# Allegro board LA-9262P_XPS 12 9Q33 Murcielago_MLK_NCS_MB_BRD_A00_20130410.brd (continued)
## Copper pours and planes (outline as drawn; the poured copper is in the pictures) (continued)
GND on TOP (solid shape): 210.81,28.25 210.81,27.92 210.8,27.9 210.8,26.6 210.85,26.55 210.85,25.57 210.77,25.49 210.12,25.49 210.04,25.57 210.04,26.5 209.91,26.63 209.79,26.63 209.71,26.64 209.64,26.63 209.29,26.63 209.25,26.64 209.21,26.64 209.14,26.67 209.11,26.74 209.11,26.78 209.11,27.21 209.11,27.25 209.11,27.28 209.11,27.71 209.11,27.75 209.11,27.78 209.11,28.21 209.11,28.27 209.18,28.33 210.73,28.33
GND on TOP (solid shape): 41.04,22.03 41.07,22.01 41.07,20.33 41.03,20.29 40.96,20.29 40.92,20.28 40.66,20.28 40.59,20.29 40.52,20.28 40.26,20.28 40.19,20.29 40.12,20.28 39.86,20.28 39.79,20.29 39.72,20.28 39.46,20.28 39.42,20.29 39.35,20.29 39.31,20.33 39.31,21.02 39.26,21.07 38.25,21.07 38.2,21.12 38.2,21.25 38.25,21.3 39.24,21.3 39.31,21.37 39.31,21.98 39.36,22.03 40.92,22.03
GND on TOP (solid shape): 221.24,48.8 221.99,47.83 223.12,48.29 230,48.29 230.35,48.15 230.49,47.8 230.49,45.15 230.35,44.8 230,44.66 222.49,44.66 221.36,45.12 220.61,44.15 220.61,42.76 217.74,42.76 217.35,43.14 217.35,44.54 218.37,45.55 218.37,49.36 219.01,50 219.92,50 220.73,50.81 221.24,50.81
GND on TOP (solid shape): 225.04,68.22 224.58,67.09 225.55,66.34 230.75,66.34 231.1,66.2 231.24,65.85 231.24,63.4 231.1,63.05 230.75,62.91 223.12,62.91 221.99,63.37 221.24,62.4 221.24,60.67 221.16,60.59 219.09,60.59 218.5,61.18 218.5,63.97 221.55,67.02 222.43,67.02 223.2,67.78 223.2,68.54 223.58,68.92 224.34,68.92 224.53,69.12 224.53,70.24 225.04,70.24
GND on TOP (solid shape): 220.61,30.05 221.34,29.08 222.48,29.52 222.49,29.54 231.2,29.54 231.55,29.4 231.69,29.05 231.69,28.51 231.69,26.19 232.39,25.49 232.39,20.16 231.69,19.46 231.69,17.24 232.79,17.24 232.99,17.04 232.99,15.76 232.79,15.56 232.14,15.56 232.14,16.07 232.48,16.07 232.48,16.73 231.13,16.73 230.96,16.91 230.96,18.62 231.18,18.84 231.18,20.07 231.29,20.17 231.29,27.4 230.17,28.51 225.75,28.51 225.23,29.03 222.75,29.03 221.39,28.55 220.24,29.43 218.37,29.43 217.35,30.44 217.35,30.95 217.86,31.46 219.85,31.46 220.1,31.71 220.1,41.14 220.61,41.14
GND on TOP (solid shape): outline of 495 points within 23.85,65.7 38.74,73.9
GND on TOP (solid shape): outline of 310 points within 0.51,0.51 231.24,88.54
GND on BOTTOM (solid shape): 139.8,81.12 139.8,77 137.71,77 137.69,77.03 137.69,81.09 137.89,81.29 139.63,81.29
GND on BOTTOM (solid shape): 200.98,22.06 200.98,19.27 200.86,19.14 198.19,19.14 198.19,22.19 198.7,22.69 200.35,22.69
GND on BOTTOM (solid shape): 212.44,66.69 212.44,65.34 212.39,65.29 209.29,65.29 209.29,66.66 209.39,66.76 212.36,66.76
GND on BOTTOM (solid shape): 30.83,22.61 30.83,20.95 30.51,20.64 28.36,20.64 27.92,21.09 27.92,22.56 28.1,22.75 30.69,22.75
GND on BOTTOM (solid shape): 51.51,66.69 51.51,66.26 51.38,66.13 44.14,66.13 44.01,66.26 44.01,67.14 44.14,67.27 50.93,67.27
GND on BOTTOM (solid shape): 66.36,21.04 66.36,19.14 66.24,19.01 63.19,19.01 63.06,19.14 63.06,21.42 63.32,21.68 65.73,21.68
GND on BOTTOM (solid shape): 79.36,47.73 79.36,46.35 79.2,46.19 69.79,46.19 69.61,46.36 69.61,47.66 69.8,47.84 79.25,47.84
GND on BOTTOM (solid shape): 167.08,34 167.08,30.96 166.95,30.82 165.46,30.82 165.34,30.94 165.34,33.95 165.46,34.07 167.01,34.07
GND on BOTTOM (solid shape): 188.72,79.53 188.72,76.54 188.48,76.3 186.57,76.3 186.13,76.74 186.13,79.46 186.38,79.72 188.54,79.72
GND on BOTTOM (solid shape): 195.65,27.03 195.65,26.1 195.52,25.97 192.49,25.97 192.35,26.11 192.35,26.96 192.53,27.14 195.54,27.14
GND on BOTTOM (solid shape): 206.09,48.58 206.09,45.45 205.95,45.32 204.53,45.32 204.13,45.71 204.13,48.3 204.49,48.65 206.01,48.65
GND on BOTTOM (solid shape): 207.02,27.28 207.02,26.13 206.88,26 203.74,26 203.6,26.14 203.6,27.29 203.71,27.4 206.89,27.4
GND on BOTTOM (solid shape): 214.81,48.82 214.81,47.25 214.64,47.08 211.97,47.08 211.76,47.29 211.76,48.74 212.02,49 214.63,49
GND on BOTTOM (solid shape): 221.24,56.82 221.24,54.43 221.2,54.39 220.82,54.39 219.86,55.36 219.86,55.9 220.81,56.86 221.2,56.86
GND on BOTTOM (solid shape): 121.08,78.66 121.08,77.75 120.86,77.53 118.64,77.53 118.44,77.74 118.44,78.73 118.51,78.8 120.94,78.8
GND on BOTTOM (solid shape): 126.37,85.43 126.37,84.68 126.2,84.51 122.87,84.51 122.84,84.54 122.84,85.46 122.91,85.52 126.28,85.52
GND on BOTTOM (solid shape): 140.2,42.72 140.2,41.37 140.11,41.27 135.25,41.27 135.17,41.35 135.17,42.62 135.46,42.92 140.01,42.92
GND on BOTTOM (solid shape): 220.16,28.6 220.16,27.48 219.75,27.07 218.29,27.07 218.15,27.2 218.15,28.75 218.36,28.96 219.8,28.96
GND on BOTTOM (solid shape): 140.99,76.95 140.99,75.86 140.91,75.78 139.14,75.78 139.03,75.88 139.03,76.77 139.11,76.85 139.85,76.85 140.04,77.04 140.9,77.04
GND on BOTTOM (solid shape): 51.51,70.33 51.51,69.43 51.25,69.18 44.14,69.18 44.01,69.3 44.01,70.19 44.14,70.32 50.55,70.32 50.75,70.51 51.33,70.51
GND on BOTTOM (solid shape): 51.51,64.2 51.51,63.46 51.12,63.08 44.27,63.08 44.01,63.33 44.01,64.1 44.14,64.22 50.68,64.22 50.82,64.37 51.34,64.37
GND on BOTTOM (solid shape): 113.95,70.93 113.95,70.42 113.92,70.39 113.51,70.39 113.26,70.14 112.28,70.14 112.22,70.21 112.22,70.78 112.46,71.02 113.86,71.02
GND on BOTTOM (solid shape): 164.79,36.28 167.84,36.28 168.09,36.03 168.09,34.89 167.84,34.63 163.39,34.63 163.14,34.89 163.14,36.28 163.39,36.54 164.54,36.54
GND on BOTTOM (solid shape): 38.48,74 38.48,71.81 34.48,71.81 33.97,71.29 31.78,71.29 31.46,71.6 31.46,73.25 31.76,73.55 33.97,73.55 34.43,74.01 38.46,74.01
GND on BOTTOM (solid shape): 78.18,21.55 78.18,19.39 77.92,19.14 74.97,19.14 74.86,19.25 74.86,19.4 74.86,19.4 74.86,21.8 74.99,21.93 77.8,21.93
GND on BOTTOM (solid shape): 115.83,24.66 119.07,24.66 119.39,24.35 119.39,19.88 118.92,19.41 118.9,19.41 118.81,19.31 114.47,19.31 113.88,19.89 113.88,24.35 114.2,24.67 115.82,24.67
GND on BOTTOM (solid shape): 116.71,81.19 116.71,79.56 116.7,79.55 115.86,79.55 115.73,79.42 115.73,78.47 115.67,78.4 115.11,78.4 115.05,78.4 114.98,78.47 114.98,79.36 115.01,79.39 115.01,81.24 116.66,81.24
GND on BOTTOM (solid shape): 150.87,41.55 150.97,41.57 152.88,41.57 153,41.44 153,40.5 152.85,40.35 149.42,40.35 149.23,40.54 149.23,41.45 149.35,41.57 150.77,41.57
GND on BOTTOM (solid shape): 146.67,82.68 146.67,81.86 146.55,81.74 146.54,81.74 146.32,81.52 141.74,81.52 141.66,81.6 141.66,82.03 141.8,82.17 142.9,82.17 143.55,82.82 146.53,82.82
GND on BOTTOM (solid shape): 171.18,34.21 172.86,34.21 172.87,34.2 172.87,32.52 171.17,32.52 171.17,33.39 171.07,33.48 170.09,33.48 170.02,33.56 170.02,34.16 170.11,34.25 171.13,34.25
GND on BOTTOM (solid shape): 23.1,25.25 23.1,23.42 22.58,22.9 21.77,22.9 21.64,23.04 21.64,23.29 21.79,23.44 22.05,23.44 22.1,23.44 22.15,23.44 22.38,23.44 22.54,23.6 22.54,24.23 22.46,24.31 22.46,25.31 22.54,25.39 22.96,25.39
GND on BOTTOM (solid shape): 207.49,68.85 207.49,67.22 207.44,67.17 206.6,67.17 206.52,67.09 206.52,66.1 206.45,66.03 205.84,66.03 205.77,66.1 205.77,67.02 205.8,67.04 205.8,68.79 205.83,68.85 205.9,68.87 207.46,68.87
GND on BOTTOM (solid shape): 216.86,70 216.86,65.62 216.8,65.56 215.93,65.56 215.85,65.64 215.85,67.14 215.58,67.41 215.58,67.58 215.59,67.59 215.64,67.73 215.64,67.87 215.61,68.11 215.46,68.29 215.46,70 215.6,70.14 216.72,70.14
GND on BOTTOM (solid shape): 24.87,77.08 24.87,75.59 24.72,75.44 24.04,75.44 23.73,75.13 23.73,73.82 23.95,73.6 24.61,73.6 24.88,73.6 25.22,73.95 29.29,73.95 29.33,73.92 29.33,71.75 29.3,71.73 25.27,71.73 24.28,70.74 22.47,70.74 22.25,70.97 22.25,74.91 22.28,74.93 22.5,75.27 22.28,75.62 22.25,75.63 22.25,76.76 22.68,77.19 24.76,77.19
GND on BOTTOM (solid shape): 225.04,68.22 224.58,67.09 225.55,66.34 230.75,66.34 231.1,66.2 231.24,65.85 231.24,63.4 231.1,63.05 230.75,62.91 223.12,62.91 221.99,63.37 221.24,62.4 221.24,60.57 219.5,60.57 218.51,61.56 218.51,63.79 223.44,68.72 224.23,68.72 224.53,69.02 224.53,70.24 225.04,70.24
GND on BOTTOM (solid shape): 221.24,50.7 221.24,48.8 221.99,47.83 223.12,48.29 230,48.29 230.35,48.15 230.49,47.8 230.49,45.15 230.35,44.8 230,44.66 222.49,44.66 221.36,45.12 220.61,44.15 220.61,42.74 217.62,42.74 216.83,43.52 216.83,47.84 219.07,50.08 220.13,50.08 220.74,50.69 220.81,50.76 221.18,50.76
GND on BOTTOM (solid shape): outline of 407 points within 61.58,77.3 82.83,79.21
GND on BOTTOM (solid shape): outline of 1532 points within 179.9,45.08 199.59,74.18
GND on BOTTOM (solid shape): outline of 424 points within 0.51,0.51 232.99,88.54
GND on IN1 (solid shape): 221.24,54.39 219.93,54.39 219.93,56.38 220.34,56.38 220.85,56.88 221.24,56.88
GND on IN1 (solid shape): 221.24,48.8 221.99,47.83 223.12,48.29 230,48.29 230.35,48.15 230.49,47.8 230.49,45.15 230.35,44.8 230,44.66 222.49,44.66 221.36,45.12 220.61,44.15 220.61,42.79 217.85,42.79 217.42,43.22 217.42,43.8 218.46,44.84 218.46,49.52 219.76,50.81 221.24,50.81
GND on IN1 (solid shape): 225.04,68.22 224.58,67.09 225.55,66.34 230.75,66.34 231.1,66.2 231.24,65.85 231.24,63.4 231.1,63.05 230.75,62.91 223.12,62.91 221.99,63.37 221.24,62.4 221.24,60.36 220.73,60.36 220.73,60.41 219.53,60.41 218.38,61.56 218.38,63.84 221.69,67.14 222.19,67.14 223.34,68.29 223.34,68.54 224.53,69.74 224.53,70.24 225.04,70.24
GND on IN1 (solid shape): outline of 313 points within 21.62,64.67 38.22,73.94
GND on IN1 (solid shape): outline of 374 points within 0.51,0.51 232.99,88.54
GND on IN2 (solid shape): 221.24,56.85 221.24,54.43 221.18,54.37 220.84,54.37 219.91,55.3 219.91,56.03 220.79,56.91 221.18,56.91
GND on IN2 (solid shape): 221.24,48.8 221.99,47.83 223.12,48.29 230,48.29 230.35,48.15 230.49,47.8 230.49,45.15 230.35,44.8 230,44.66 222.49,44.66 221.36,45.12 220.61,44.15 220.61,42.81 217.8,42.81 217.01,43.6 217.01,48.35 219.43,50.76 221.24,50.76
GND on IN2 (solid shape): 225.04,68.22 224.58,67.09 225.55,66.34 230.75,66.34 231.1,66.2 231.24,65.85 231.24,63.4 231.1,63.05 230.75,62.91 223.12,62.91 221.99,63.37 221.24,62.4 221.24,60.81 221.13,60.69 220.73,60.69 220.43,61 219.15,61 218.51,61.63 218.51,64.07 221.36,66.92 221.63,66.92 223.44,68.72 224.28,68.72 224.53,68.97 224.53,70.22 225.04,70.22
GND on IN2 (solid shape): outline of 291 points within 21.38,65.43 38.21,73.87
GND on IN2 (solid shape): outline of 379 points within 0.51,0.51 232.99,88.54
GND on IN3 (solid shape): 221.24,56.79 221.24,54.41 221.2,54.37 220.84,54.37 219.93,55.27 219.93,56.01 220.81,56.88 221.15,56.88
GND on IN3 (solid shape): 221.24,50.7 221.24,48.8 221.99,47.83 223.12,48.29 230,48.29 230.35,48.15 230.49,47.8 230.49,45.15 230.35,44.8 230,44.66 222.49,44.66 221.36,45.12 220.61,44.15 220.61,42.74 217.77,42.74 216.99,43.52 216.99,48.07 219.15,50.23 220.25,50.23 220.84,50.81 221.13,50.81
GND on IN3 (solid shape): 225.04,68.22 224.58,67.09 225.55,66.34 230.75,66.34 231.1,66.2 231.24,65.85 231.24,63.4 231.1,63.05 230.75,62.91 223.12,62.91 221.99,63.37 221.24,62.4 221.24,60.62 219.15,60.62 218.46,61.3 218.46,64 221.33,66.87 221.56,66.87 223.44,68.75 224.41,68.75 224.53,68.87 224.53,70.24 225.04,70.24
GND on IN3 (solid shape): outline of 179 points within 22.72,68.49 38.17,74.6
GND on IN3 (solid shape): outline of 389 points within 0.51,0.51 232.99,88.54
GND on IN4 (solid shape): 221.24,56.85 221.24,54.41 221.2,54.37 220.84,54.37 219.93,55.27 219.93,56.01 220.81,56.88 221.2,56.88
GND on IN4 (solid shape): 221.24,50.66 221.24,48.8 221.99,47.83 223.12,48.29 230,48.29 230.35,48.15 230.49,47.8 230.49,45.15 230.35,44.8 230,44.66 222.49,44.66 221.36,45.12 220.61,44.15 220.61,42.76 217.72,42.76 216.92,43.56 216.92,48.77 218.92,50.76 221.14,50.76
GND on IN4 (solid shape): 225.04,68.22 224.58,67.09 225.55,66.34 230.75,66.34 231.1,66.2 231.24,65.85 231.24,63.4 231.1,63.05 230.75,62.91 223.12,62.91 221.99,63.37 221.24,62.4 221.24,60.67 219.3,60.67 218.49,61.48 218.49,63.97 221.46,66.94 221.66,66.94 223.44,68.72 224.31,68.72 224.53,68.95 224.53,70.24 225.04,70.24
GND on IN4 (solid shape): outline of 113 points within 25.1,69.66 38.17,74.39
GND on IN4 (solid shape): outline of 383 points within 0.51,0.51 232.99,88.54
GND on GND1: outline of 201 points within 0.51,0.51 232.99,88.54 ; 3 cut-outs
GND on GND2, GND4: outline of 201 points within 0.51,0.51 232.99,88.54 ; 2 cut-outs
GND on GND3: outline of 323 points within 0.51,0.51 232.99,88.54 ; 2 cut-outs
GND on VCC: 60.79,13.75 58.5,11.46 56.21,13.75 56.21,16.55 55.77,17.62 54.7,18.06 47.56,18.06 47.56,18.08 47.64,18.33 47.56,18.57 47.56,23.31 46.65,24.22 14.43,24.22 13.65,23.44 13.65,18.56 13.58,18.33 13.65,18.09 13.65,18.06 1,18.06 0.65,18.2 0.51,18.55 0.51,28 0.58,28.25 0.77,28.43 9.82,35.93 15.08,46.44 21.99,46.44 22.01,46.42 22.22,46.42 22.25,46.44 22.26,46.44 22.41,46.59 22.41,46.6 26.07,50.25 29.37,50.25 35.47,56.35 45.88,56.35 52.74,63.21 55.79,63.21 57.57,64.99 63.41,64.99 63.92,65.49 83.77,65.49 84.13,65.14 84.13,65.13 84.52,64.74 84.53,64.74 85.54,63.74 85.54,63.59 85.8,63.59 87.72,63.59 88.21,63.1 88.21,61.71 88.99,60.92 91.52,60.92 92.79,59.65 94.06,59.65 96.32,57.39 96.32,54.21 98.62,51.93 98.62,51.29 99.15,50.76 105.2,50.76 105.35,50.91 105.35,50.92 110.91,56.48 111.46,56.48 112.35,55.59 124.29,55.59 126.55,53.32 126.55,29.28 125.68,28.41 120.86,28.41 116.67,24.22 76.66,24.22 75.5,23.05 75.5,18.06 62.3,18.06 61.23,17.62 60.79,16.55
GND on VCC: 230.49,45.15 230.35,44.8 230,44.66 222.49,44.66 222.06,45.06 221.48,45.15 217.39,49.24 201.26,49.24 200.35,48.33 200.35,46.19 196.14,46.19 195.52,46.8 195.51,61.2 198.32,64 198.32,70.21 203.78,75.68 203.78,78.72 204.13,78.59 204.5,78.54 213.08,78.54 214.04,78.88 214.56,79.75 217,81.74 219.44,79.75 219.96,78.88 220.92,78.54 230.75,78.54 231.1,78.4 231.24,78.05 231.24,76.75 231.1,76.4 230.75,76.26 225.55,76.26 224.58,75.51 225.04,74.38 225.04,68.22 224.58,67.09 225.55,66.34 230.75,66.34 231.1,66.2 231.24,65.85 231.24,63.4 231.1,63.05 230.75,62.91 223.12,62.91 221.99,63.37 221.24,62.4 221.24,48.8 221.99,47.83 223.12,48.29 230,48.29 230.35,48.15 230.49,47.8
GND on VCC: 18.18,63.46 21.01,79.51 21.01,88.05 21.15,88.4 21.5,88.54 23.39,88.54 23.57,88.5 23.73,88.4 25.29,86.84 31.43,86.84 32.56,86.57 33.44,85.81 34.33,84.88 35.42,84.19 34.6,83.38 34.6,75.62 30.3,71.31 30.3,70.93 29.94,70.57 29.43,70.57 22.32,63.46
GND on VCC: 232.99,1 232.85,0.65 232.5,0.51 230,0.51 229.65,0.65 229.51,1 229.51,1.5 229.07,2.57 228,3.01 224.5,3.01 224.15,3.15 224.01,3.5 224.01,14.55 223.24,16.74 221.28,17.97 221.37,18.06 221.37,29.07 222.01,29.12 222.49,29.54 231.2,29.54 231.55,29.4 231.69,29.05 231.69,26.19 232.39,25.49 232.39,20.16 231.69,19.46 231.69,17.24 232.79,17.24 232.99,17.04 232.99,15.76 232.79,15.56 231.69,15.56 231.69,13.54 232.79,13.54 232.99,13.34 232.99,12.16 232.79,11.96 231.69,11.96 231.69,9.94 232.79,9.94 232.99,9.74 232.99,8.56 232.79,8.36 231.69,8.36 231.69,6.34 232.79,6.34 232.99,6.14 232.99,4.96 232.79,4.76 231.69,4.76 231.69,2.74 232.79,2.74 232.99,2.54
GND on GND5: outline of 201 points within 0.51,0.51 232.99,88.54 ; 1 cut-out
VDD_+1.2V on TOP (solid shape): 44.94,21.82 44.94,21.81 45.17,21.62 45.47,21.65 45.85,21.65 45.99,21.61 46.13,21.61 46.16,21.62 46.25,21.53 46.25,21.02 46.12,20.89 44.09,20.89 43.83,20.64 43.83,20 43.71,19.88 43.33,19.88 43.2,20 43.2,20.43 43.33,20.7 43.21,20.98 43.2,21 43.2,21.02 43.07,21.15 43.07,21.78 43.2,21.91 44.85,21.91
VIN on TOP (solid shape): 173.43,42.65 173.43,41.17 172.97,40.72 171.87,40.72 171.87,40.74 169.15,40.74 169.01,40.88 169.01,41.98 169.22,42.2 169.22,42.82 169.34,42.94 173.14,42.94
VIN on TOP (solid shape): 195.24,80.01 198.67,80.01 198.94,79.75 198.94,78.89 198.75,78.7 195.69,78.7 195.42,78.97 194.83,78.97 194.57,79.22 193.05,79.22 192.91,79.36 192.91,80.4 193.1,80.59 194.66,80.59
VIN on IN2 (solid shape): 173.55,42.13 173.55,41.24 173.43,41.11 171.65,41.11 171.27,41.49 169.23,41.49 169.11,41.62 169.11,43.14 169.36,43.4 172.28,43.4
VIN on IN2 (solid shape): 147.23,48.48 147.23,46.37 146.31,45.46 144.83,45.46 144.53,45.15 144.53,44.55 144.22,44.24 142.3,44.24 141.91,44.63 141.91,45.81 142.07,45.97 144.78,45.97 144.79,45.91 144.8,45.86 144.82,45.8 144.85,45.76 144.88,45.71 144.92,45.67 144.97,45.64 145.02,45.61 145.07,45.6 145.12,45.59 145.18,45.58 145.23,45.59 145.29,45.6 145.34,45.63 145.39,45.66 145.43,45.69 145.47,45.73 145.5,45.78 145.52,45.83 145.54,45.88 145.55,45.94 145.55,45.99 145.54,46.05 145.52,46.1 145.5,46.15 145.47,46.2 145.43,46.24 145.39,46.28 145.34,46.31 145.29,46.33 145.23,46.34 145.18,46.35 145.12,46.35 145.07,46.34 145.02,46.32 144.97,46.29 144.92,46.26 144.88,46.22 144.85,46.18 144.82,46.13 144.8,46.08 144.79,46.02 144.78,45.97 142.07,45.97 143.59,47.49 144.04,47.49 144.79,48.23 145.84,48.23 146.36,48.75 146.95,48.75
VIN on VCC: 169.97,40.73 169.09,41.6 169.09,44.54 170.09,44.54 172.23,46.69 172.23,48.35 175.53,51.65 175.53,56.89 175.41,57.14 172.28,60.27 172.28,69.02 173.92,70.66 173.92,74.28 176.31,76.67 188.63,76.67 192.44,80.48 197.78,80.48 198.43,81.14 198.43,82.15 198.71,82.07 199,82.04 202.5,82.04 202.85,81.9 202.99,81.55 202.99,80.05 203.06,79.59 203.27,79.17 203.27,75.89 197.81,70.43 197.81,64.21 195.15,61.56 190.07,61.56 189.41,60.9 189.41,49.72 185.36,45.67 185.36,45.66 180.43,40.73
1.2_PGND on TOP (solid shape): 116.39,48.39 116.39,47.35 116.66,47.08 119.64,47.08 119.69,47.03 119.69,45.94 119.56,45.81 119.56,45.05 119.56,44.2 119.38,44.02 118.18,44.02 118.04,44.16 118.04,44.92 117.79,45.17 117.02,45.17 116.83,45.36 116.83,45.91 116.49,46.25 116.48,46.25 115.96,46.77 115.6,46.77 115.53,46.85 115.53,48.43 115.64,48.54 116.24,48.54
1.2_PGND on GND1: 118.53,44.28 118.42,44.39 118.42,44.9 117.89,45.43 115.75,45.43 115.54,45.63 115.54,49.09 118.35,51.9 122.25,51.9 122.61,51.55 122.61,46.42 121.75,45.55 121.24,45.55 119.97,44.28
+INV_PWR_SRC on TOP (solid shape): 160.22,82.01 160.53,82.01 161,81.54 161.02,81.43 160.93,81.37 160.6,80.86 161.18,80.68 161.22,80.7 161.27,80.7 161.47,80.7 161.55,80.62 161.55,80.02 161.51,79.98 161.51,79.64 161.82,79.34 164.68,79.34 164.68,79.33 165.93,79.33 166.95,78.31 166.95,76.49 166.76,76.3 165.96,76.3 165.92,76.34 165.92,76.62 165.49,77.05 161.38,77.05 160.57,77.87 160.57,78.3 160.72,78.44 160.78,78.65 160.61,78.96 160.25,78.99 160.22,78.98 159.85,79.35 158.64,79.35 158.56,79.43 158.56,80.45 157.63,81.38 157.63,81.97 157.67,82.01 160.22,82.01
+INV_PWR_SRC on BOTTOM (solid shape): 160.28,81.66 160.28,80.58 160.18,80.48 159.49,80.48 159.39,80.38 159.39,79.08 159.34,79.03 158.68,79.03 158.6,79.11 158.6,80.3 158.44,80.47 158.44,81.72 158.55,81.84 160.1,81.84
+LCDVDD on TOP (solid shape): 171.67,75.64 171.67,75.07 171.7,75.04 171.7,73.65 171.7,73.65 171.7,73.51 171.5,73.32 170.46,73.32 170.21,73.56 170.21,75.45 170.53,75.77 171.53,75.77
+LCDVDD on BOTTOM (solid shape): 171.87,76.58 171.87,75.82 171.69,75.64 171.69,75.48 171.68,75.45 171.69,75.42 171.69,74.78 171.52,74.62 170.29,74.62 170.16,74.76 170.16,76.54 170.26,76.64 171.81,76.64
+LCDVDD on BOTTOM (solid shape): 179.89,80.28 179.89,79.08 180.06,78.92 180.06,77.99 179.9,77.84 179.9,77.38 179.77,77.24 179.77,76.67 179.62,76.52 177.72,76.52 177.58,76.66 177.58,78.77 177.69,78.88 178.9,78.88 179.1,79.08 179.1,80.3 179.18,80.38 179.79,80.38
+LCDVDD on VCC: 170.22,74.51 169.86,74.87 169.86,79.49 170.72,80.35 180.17,80.35 181.16,79.36 181.16,77.56 180.77,77.18 176.1,77.18 173.43,74.51
+VCHGR on BOTTOM (solid shape): outline of 118 points within 135.12,32.74 142.81,41.87
+VREFCA on IN1 (solid shape): outline of 5910 points within 16.24,28.66 67.76,34.51
+VREFCA on IN2 (solid shape): outline of 4646 points within 55.06,28.41 103.83,33.62
+VREFDQ_A on IN1 (solid shape): outline of 3930 points within 24.84,34.89 63.19,43.27
+VREFDQ_B on IN2 (solid shape): outline of 6567 points within 64.08,34.25 110.69,42.63
ADPIN on TOP (solid shape): 196.51,84 196.51,81.94 197.38,81.08 197.38,80.57 197.2,80.39 196.44,80.39 196.44,80.39 195.21,80.39 194.69,80.91 193.06,80.91 192.96,81 192.96,82.06 193.38,82.48 193.38,83.82 193.59,84.04 196.48,84.04
ADPIN on BOTTOM (solid shape): 196.2,83.22 196.2,80.81 195.65,80.26 190.94,80.26 190.7,80.5 190.7,82.11 190.98,82.39 192.43,82.39 193.36,83.32 196.09,83.32
B+ on TOP (solid shape): 201.45,46.24 201.45,44.31 201.25,44.11 200.21,44.11 200.01,44.31 200.01,46.11 200.25,46.35 201.35,46.35
B+ on TOP (solid shape): 210.67,70.41 210.67,69.61 210.24,69.18 206.2,69.18 206.02,69.35 206.02,70.48 206.12,70.58 210.5,70.58
B+ on TOP (solid shape): 201.99,36.58 201.99,35.57 202.45,35.12 202.45,34.43 202.22,34.2 201.73,34.2 201.23,34.71 200.67,34.71 200.58,34.8 200.58,36.58 200.69,36.69 201.87,36.69
B+ on TOP (solid shape): 203.35,26.13 203.35,24.99 203.18,24.82 202.31,24.82 201.9,24.41 201.9,22.03 198.71,18.83 193.1,18.83 192.92,19.01 192.92,20.54 192.92,20.54 192.92,20.9 193.21,21.19 196.54,21.19 198.58,23.23 198.58,25.29 199.57,26.28 203.2,26.28
B+ on TOP (solid shape): 166.05,85.94 166.05,85.05 165.92,84.92 163.51,84.92 163.39,85.04 163.4,85.07 163.43,85.27 163.38,85.46 163.38,85.47 163.38,85.81 163.76,86.19 165.79,86.19
B+ on TOP (solid shape): 122.46,83.14 122.46,80.57 121.59,79.69 118.81,79.69 118.76,79.64 118.75,79.64 118.37,79.26 116.61,79.26 116.61,79.26 116.55,79.26 115.87,78.58 115.04,78.58 114.96,78.66 114.96,81.08 115.36,81.47 117.97,81.47 118.28,81.77 119.39,81.77 120.19,82.58 120.26,82.66 120.32,82.75 120.45,82.88 120.45,83.11 120.62,83.28 120.63,83.28 120.96,83.62 121.98,83.62
B+ on TOP (solid shape): outline of 109 points within 157.51,79.53 163.84,83.91
B+ on BOTTOM (solid shape): 170.38,25.17 170.38,23.44 170.05,23.11 167,23.11 166.67,23.44 166.67,25.25 166.86,25.44 170.1,25.44
B+ on BOTTOM (solid shape): 86.84,21.19 86.84,19.56 86.54,19.26 83.8,19.26 83.52,19.54 83.52,20.96 83.85,21.29 86.74,21.29
B+ on BOTTOM (solid shape): 122.41,83.17 122.41,80.73 122.16,80.48 121.41,80.48 121.41,81.01 120.95,81.01 120.95,80.48 120.58,80.48 120.12,80.94 120.12,82.88 121,83.75 121.83,83.75
B+ on BOTTOM (solid shape): 191.92,29.98 191.92,27.85 191.84,27.77 187.35,27.77 186.42,28.71 184.37,28.71 184.29,28.78 184.29,29.84 184.38,29.92 186.45,29.92 187.1,30.57 191.33,30.57
B+ on BOTTOM (solid shape): 211.04,70.27 211.04,69.06 210.93,68.95 210.46,68.95 210.46,69.48 210.02,69.48 210.02,68.95 209.04,68.95 208.92,69.06 208.92,69.25 208.91,69.27 208.91,69.31 208.77,69.45 208.77,69.45 208.69,69.54 208.69,70.31 208.84,70.47 210.84,70.47
B+ on BOTTOM (solid shape): 39.55,82.14 39.55,81.18 39.56,81.17 39.56,78.12 39.21,77.77 36.88,77.77 36.87,77.78 36.87,79.22 36.99,79.34 36.99,80.78 36.98,80.8 36.46,80.8 36.46,81.04 36.99,81.04 37,81.05 37,81.6 36.46,81.6 36.46,81.83 37,81.83 37,82.32 37.13,82.45 39.24,82.45
B+ on BOTTOM (solid shape): outline of 2376 points within 135.17,35.9 157.13,83.02
B+ on IN1 (solid shape): outline of 5778 points within 190.6,18.83 218.23,70.6
B+ on IN4 (solid shape): outline of 478 points within 119.96,76.89 152.6,85.94
B+ on VCC: 108.8,73.06 106.84,75.02 103.85,75.02 100.67,78.19 59.39,78.19 56.85,75.65 35.11,75.65 35.11,83.17 35.93,83.99 39.04,83.98 41.56,85.81 42.44,86.57 43.57,86.84 111.43,86.84 112.56,86.57 113.44,85.81 117.5,83.74 121.56,85.81 122.44,86.57 123.57,86.84 131.39,86.84 131.61,86.86 131.83,86.91 131.83,86.64 132.13,86.35 134.19,86.35 136.07,84.46 136.07,83.7 136.37,83.4 136.79,83.4 136.81,83.42 137.34,82.99 138,82.84 141,82.84 141.86,83.11 142.41,83.81 142.44,83.78 143.22,83.78 144.11,84.67 150.76,84.67 151.06,84.97 151.06,85.06 151.33,85.32 151.33,85.36 151.37,85.36 151.67,85.65 151.67,85.68 151.9,85.91 151.9,86.02 152.03,86.15 152.03,86.71 152.05,86.73 152.05,86.84 165.32,86.84 165.57,86.59 154.38,75.4 132.73,75.4 125.92,82.21 122.75,82.21 121.39,80.85 121.39,78.35 119.84,76.8 113.49,76.8 109.76,73.06
B+ on VCC: 132.85,18.2 132.5,18.06 76,18.06 76,22.83 76.02,22.84 76.02,22.86 76.87,23.71 116.88,23.71 121.07,27.9 130.97,27.9 141.39,38.32 152.86,38.32 153.22,37.96 153.22,31.61 160.73,24.09 198.09,24.09 198.57,23.61 198.57,18.56 198.07,18.06 179.5,18.06 179.15,18.2 178.57,19.62 177.5,20.06 134.5,20.06 133.43,19.62
BATT+ on BOTTOM (solid shape): outline of 345 points within 126.47,30.57 134.27,41.81
BATT++ on BOTTOM (solid shape): outline of 632 points within 119.97,19.27 131.01,41.08
BTST on TOP (solid shape): 152.92,43.09 152.92,42.35 152.79,42.23 152.07,42.23 151.49,42.81 150.47,42.81 150.4,42.88 150.4,43 150.48,43.07 151.98,43.07 152.1,43.19 152.81,43.19
CHG_LGATE on TOP (solid shape): 157.64,33.94 157.64,33.14 157.53,33.03 156.52,33.03 156.4,33.15 156.4,33.93 156.59,34.12 157.45,34.12
CHG_LGATE on TOP (solid shape): 150.43,42.13 150.93,42.13 151.06,42 151.06,41.46 150.78,41.18 150.18,41.18 150.08,41.27 150.08,42.16 150.17,42.25 150.3,42.25
CHG_LGATE on IN2 (solid shape): 157.68,33.62 157.68,32.73 157.55,32.6 154.76,32.6 154.5,32.85 154.5,33.62 154.63,33.74 157.55,33.74
CHG_LGATE on IN2 (solid shape): 151.28,42.04 151.28,42.02 151.29,41.92 151.32,41.83 151.33,41.82 151.33,41.11 151.07,40.86 149.93,40.86 149.68,41.11 149.68,42 149.93,42.25 150.57,42.25 150.82,42.15 151.07,42.26
CHG_LX on TOP (solid shape): 155.59,45.34 155.59,39.75 156.14,39.2 159.44,39.2 159.7,38.95 159.7,36.92 160.46,36.16 160.46,35.65 161.38,34.73 161.38,33.97 160.93,33.52 158.28,33.52 158.09,33.71 158.09,35.73 156.39,37.43 154.11,37.43 153.85,37.68 153.85,39.97 154.66,40.77 154.66,41.08 154.5,41.24 154.5,41.42 154.49,41.43 154.49,44.89 154.29,45.1 153.4,45.1 153.22,44.92 153.22,44.16 153.04,43.98 151.78,43.98 151.61,43.81 150.48,43.81 150.41,43.88 150.41,44 150.49,44.08 151.38,44.08 151.7,44.41 151.71,44.41 151.95,44.55 152.09,44.79 152.1,44.81 152.11,44.89 152.12,44.95 152.12,45.04 152.5,45.43 152.62,45.61 152.66,45.83 152.69,45.91 152.76,45.94 155,45.94
CHG_LX on BOTTOM (solid shape): outline of 85 points within 157.93,33.74 162.38,40.98
CHG_UGATE on TOP (solid shape): 152.99,43.75 152.99,43.42 152.89,43.32 152,43.32 151.99,43.31 150.49,43.31 150.41,43.38 150.41,43.51 150.49,43.59 151.58,43.59 151.82,43.83 152.92,43.83
CHG_UGATE on TOP (solid shape): 161.86,38.89 161.86,36.34 161.92,36.28 161.92,35.63 161.77,35.48 160.88,35.48 160.71,35.65 160.71,36.16 160.13,36.74 160.13,38.93 160.29,39.09 161.66,39.09
CHG_UGATE on IN2 (solid shape): 153.74,43.52 153.74,42.76 153.61,42.63 151.71,42.63 151.58,42.76 151.58,43.52 151.84,43.78 153.49,43.78
CHG_UGATE on IN2 (solid shape): 162.12,38.32 162.12,35.78 161.87,35.52 160.85,35.52 160.6,35.78 160.6,38.32 160.85,38.57 161.87,38.57
COMP on TOP (solid shape): 31.08,85.45 31.08,85.18 31.53,84.72 31.96,84.72 32.19,84.49 32.19,83.65 32.06,83.53 31.43,83.53 31.3,83.4 31.3,82.89 31.17,82.77 30.41,82.77 30.28,82.89 30.28,85.4 30.46,85.58 30.95,85.58
CPU_B+ on BOTTOM (solid shape): 38.75,67.96 38.75,63.92 38.49,63.65 35.74,63.65 35.5,63.89 35.5,67.53 36.27,68.29 38.42,68.29
CPU_B+ on BOTTOM (solid shape): outline of 428 points within 23.91,73.88 36.97,82.38
CPU_B+ on IN1 (solid shape): outline of 945 points within 23.91,66.26 41.35,81.27
DCIN_GND on BOTTOM (solid shape): 192.76,79.54 192.76,75.78 192.48,75.5 190.21,75.5 190.08,75.37 189.52,75.37 189.25,75.64 189.25,78.04 189.96,78.04 189.96,77.99 189.98,77.93 190,77.88 190.02,77.83 190.06,77.79 190.1,77.75 190.14,77.72 190.19,77.69 190.25,77.67 190.3,77.66 190.36,77.66 190.41,77.67 190.47,77.68 190.52,77.7 190.56,77.73 190.61,77.77 190.64,77.81 190.68,77.85 190.7,77.9 190.72,77.96 190.72,78.01 190.72,78.07 190.72,78.12 190.7,78.18 190.68,78.23 190.64,78.28 190.61,78.32 190.56,78.35 190.52,78.38 190.47,78.4 190.41,78.42 190.36,78.42 190.3,78.42 190.25,78.41 190.19,78.39 190.14,78.37 190.1,78.34 190.06,78.3 190.02,78.25 190,78.2 189.98,78.15 189.96,78.1 189.96,78.04 189.25,78.04 189.25,79.49 189.59,79.83 192.47,79.83
DH_+1.2V on TOP (solid shape): 50.07,22.82 51,22.82 51.07,22.74 51.07,22.45 50.95,22.33 49.93,22.33 49.82,22.44 49.49,22.44 49.38,22.34 49.38,21.81 49.23,21.65 48.83,21.65 48.67,21.81 48.67,22.87 48.8,23 49.89,23
DH_+1.2V on TOP (solid shape): 43.61,24.33 43.61,23.86 43.71,23.76 43.71,23.75 43.74,23.62 43.8,23.5 43.8,23.49 43.8,23.1 43.68,22.98 43.34,23.08 42.99,22.96 42.98,22.95 42.79,22.95 42.68,23.06 42.68,23.55 42.52,23.71 41,23.71 40.76,23.46 40.76,22.33 40.7,22.28 40.57,22.28 40.52,22.33 40.52,23.88 40.44,23.96 40.44,24.27 40.62,24.45 43.49,24.45
DH_+1.2V on IN1 (solid shape): 44.65,23.33 44.65,22.57 44.52,22.44 43.25,22.44 42.74,22.95 42.74,23.2 43,23.46 44.52,23.46
DH_+1.2V on IN1 (solid shape): 50.36,22.95 50.36,21.3 50.11,21.04 48.97,21.04 48.71,21.3 48.71,22.95 48.84,23.08 50.24,23.08
DL_+1.2V on TOP (solid shape): 42.84,22.62 42.84,22.29 42.69,22.14 42.41,22.14 42.16,21.88 41.35,21.88 41.28,21.95 41.28,22.17 41.85,22.75 42.72,22.75
DL_+1.2V on TOP (solid shape): 53.8,22.06 53.8,21.73 53.63,21.55 51.67,21.55 51.03,20.91 50.22,20.91 50.09,21.04 50.09,21.85 50.22,21.98 51.16,21.98 51.37,22.19 53.68,22.19
DL_+1.2V on IN4 (solid shape): 53.82,22.26 53.82,21.7 53.54,21.42 50.49,21.42 50.36,21.55 50.36,22.31 50.49,22.44 53.64,22.44
DL_+1.2V on IN4 (solid shape): 42.79,22.82 42.92,22.8 43.05,22.82 43.06,22.82 43.42,22.82 43.43,22.82 43.56,22.8 43.69,22.82 43.69,22.82 43.89,22.82 43.89,21.81 42.11,21.81 41.73,22.19 41.73,22.57 41.98,22.82 42.78,22.82
INV_PWM_R on TOP (solid shape): 159.99,78.95 159.99,78.35 159.9,78.14 160,77.93 160,77.8 161.97,75.82 162.63,75.82 162.63,75.82 163.28,75.82 163.76,75.34 163.91,75.34 164.03,75.22 164.03,73.05 163.87,72.88 162.52,72.88 161.96,73.44 160.74,73.44 160.43,73.75 160.43,75.67 160.26,75.85 159.23,75.85 159.1,75.97 159.1,77.3 158.8,77.61 158.8,79.05 158.93,79.18 159.76,79.18
P1 on TOP (solid shape): 164.92,45.03 164.92,44.19 164.57,43.85 164.57,41.56 165.09,41.04 165.09,40.61 165.3,40.39 165.74,40.39 166,40.13 166,39.53 165.96,39.46 165.61,39.11 165.61,38.64 165.94,38.32 166.24,38.32 166.95,37.61 166.98,37.57 168.12,37.57 168.21,37.49 168.21,36.92 167.23,36.92 166.94,36.85 166.72,36.66 166.7,36.64 166.5,36.64 166.3,36.44 166.3,36.13 166.48,35.95 166.52,35.95 166.59,35.93 166.66,35.93 166.7,35.93 166.72,35.91 166.94,35.72 167.23,35.65 167.69,35.65 167.73,35.55 167.73,35.44 167.64,35.39 165.6,35.39 164.64,36.36 164.63,36.37 164.54,36.53 164.38,36.62 164.37,36.63 164.1,36.9 164.1,39.5 163.38,40.22 163.38,45.05 163.63,45.3 164.65,45.3
REGN on TOP (solid shape): 151.95,42.13 151.95,40.83 153.48,39.3 153.48,38.5 153.32,38.35 152.25,38.35 152.15,38.45 152.15,39.13 151.67,39.61 151.09,39.61 150.93,39.76 150.93,40.59 151.31,40.97 151.31,42.13 151.12,42.32 150.49,42.32 150.41,42.4 150.41,42.5 150.48,42.57 151.51,42.57
SNUB_1.5VSP on BOTTOM (solid shape): 113.14,77.85 113.14,76.9 113.06,76.82 111.46,76.82 111.05,77.24 109.32,77.24 109.2,77.35 109.2,77.86 109.34,78 111.04,78 111.05,78 112.99,78
SNUB_+1.2V on BOTTOM (solid shape): 46.04,21.34 46.04,19.06 45.81,18.83 43.7,18.83 43.73,19.1 43.67,19.38 43.67,19.47 43.76,19.52 44.27,19.52 44.77,20.03 44.77,21.29 44.99,21.5 45.88,21.5
SNUB_CHG on TOP (solid shape): 155.66,36.95 155.66,35.95 155.53,35.81 152.74,35.81 152.65,35.9 152.65,36.8 152.75,36.89 153.56,36.89 153.72,37.05 155.56,37.05
SNUB_PHASE1 on TOP (solid shape): 34.76,71.2 34.76,70.42 34.55,70.21 31.75,70.21 31.69,70.28 31.69,71.24 31.79,71.34 34.61,71.34
SNUB_PHASE2 on TOP (solid shape): 23.85,70.36 23.68,70.19 21.2,70.19 21.02,70.37 21.02,71.43 21.14,71.55 23.85,71.55
SW_+1.2V on TOP (solid shape): 42.51,23.41 42.51,23 42.39,22.87 41.9,22.87 41.9,22.88 41.62,22.88 41.13,22.39 41.13,22.26 41.13,22.26 41,22.26 40.94,22.32 40.94,23.21 41.23,23.51 42.41,23.51
SW_+1.2V on TOP (solid shape): 51.08,24.73 51.08,23.12 51.01,23.05 50.12,23.05 49.97,23.2 48.75,23.2 48.5,22.95 48.5,21.55 48.62,21.42 49.26,21.42 49.31,21.42 49.51,21.22 49.51,19.06 49.33,18.88 46.86,18.88 46.6,19.14 46.6,24.66 46.77,24.83 50.98,24.83
SW_+1.2V on BOTTOM (solid shape): 42.7,25.41 42.7,25.19 42.65,24.79 42.99,24.57 43.06,24.54 43.09,24.47 43.09,23.66 43.05,23.58 42.97,23.56 42.63,23.42 42.56,23.06 42.54,22.97 42.46,22.92 41.43,22.92 41.31,23.05 41.31,23.97 41.94,24.61 41.94,25.4 42.01,25.47 42.63,25.47
SW_+1.2V on BOTTOM (solid shape): outline of 108 points within 46.51,18.95 52.61,25.36
SW_+1.05VS on BOTTOM (solid shape): 136.34,82.5 136.34,80.86 136.52,80.68 137.39,80.68 137.54,80.53 137.54,78.89 137.47,78.83 133.2,78.83 133.05,78.98 133.05,83.55 133.12,83.62 135.22,83.62
SW_PHASE_1 on TOP (solid shape): 33.4,69.39 33.4,67.54 33.37,67.51 31.77,67.51 31.71,67.58 31.71,69.42 31.78,69.49 33.3,69.49
SW_PHASE_1 on BOTTOM (solid shape): 36.99,70.23 36.37,69.61 36.37,68.9 35.07,67.6 35.07,65.65 34.92,65.49 31.44,65.49 31.33,65.61 31.33,68.16 30.56,68.16 30.56,65.66 30.4,65.49 28.66,65.49 28.35,65.81 28.35,69.34 28.56,69.54 34.78,69.54 34.79,69.49 34.8,69.43 34.82,69.38 34.85,69.34 34.89,69.29 34.93,69.26 34.97,69.23 35.02,69.2 35.08,69.19 35.13,69.18 35.19,69.18 35.24,69.19 35.3,69.2 35.35,69.23 35.39,69.26 35.44,69.29 35.47,69.34 35.5,69.38 35.52,69.43 35.54,69.49 35.54,69.54 35.54,69.6 35.53,69.65 35.51,69.71 35.49,69.76 35.45,69.8 35.42,69.84 35.37,69.88 35.32,69.9 35.27,69.92 35.22,69.94 35.16,69.94 35.11,69.94 35.05,69.92 35,69.9 34.95,69.88 34.91,69.84 34.87,69.8 34.84,69.76 34.81,69.71 34.79,69.65 34.78,69.6 34.78,69.54 28.56,69.54 29.05,70.03 32.11,70.03 32.93,70.86 33.97,70.86 34.73,71.62 36.99,71.62
SW_PHASE_2 on TOP (solid shape): 25.33,69.18 25.33,67.86 25.12,67.65 21.17,67.65 20.96,67.86 20.96,69.26 21.13,69.43 25.08,69.43
SW_PHASE_2 on BOTTOM (solid shape): 27.82,71.53 27.82,70.46 27.58,70.23 27.2,70.23 27,70.03 27,69.6 26.51,69.11 26.51,68.79 26.74,68.56 26.74,65.75 26.36,65.36 23.98,65.36 23.77,65.58 23.77,68.2 22.93,68.2 22.93,65.66 22.64,65.37 20.65,65.37 20.28,65.75 20.28,69.84 20.78,70.34 24.36,70.34 25.56,71.54 27.81,71.54
VLDOIN_+1.2V on TOP (solid shape): 31.98,23.46 32.42,23.46 32.42,24 33.33,24 33.61,23.71 33.61,22.86 33.37,22.62 32.71,22.62 32.31,22.22 32.31,20.79 32.16,20.64 30.88,20.64 30.68,20.84 30.68,22.59 31.66,23.58 31.66,23.92 31.73,24 31.98,24
VLDOIN_+1.2V on IN4 (solid shape): 32.67,21.53 32.67,20.64 32.42,20.38 30.64,20.38 30.39,20.64 30.39,21.53 30.64,21.78 32.42,21.78
VLDOIN_+1.2V on IN4 (solid shape): 40.04,23.94 40.04,22.8 39.91,22.67 39.28,22.67 38.89,23.05 38.87,23.05 38.86,23.06 38.67,23.1 38.49,23.05 38.01,23.05 37.75,23.3 37.75,24.07 37.88,24.19 39.78,24.19
N13308186 on TOP (solid shape): 169.11,40.6 172.93,40.6 173.16,40.36 173.16,39.52 173.02,39.38 173.02,38.88 172.84,38.7 171.56,38.7 171.56,38.7 169.8,38.7 169.61,38.7 168.33,38.7 168.21,38.82 168.21,40.35 168.46,40.6 169.11,40.6
N13308194 on TOP (solid shape): 172.14,38.53 172.28,38.53 172.49,38.32 172.49,35.19 172.27,34.97 169.42,34.97 169.05,35.34 169.03,35.34 169.03,35.39 169.01,35.49 168.97,35.58 168.97,35.85 169.04,35.93 170.42,35.93 170.54,35.93 170.59,35.97 170.67,36.03 170.73,36.11 170.77,36.16 170.77,36.46 170.57,36.66 169.04,36.66 168.97,36.74 168.97,37.3 169.09,37.43 169.6,37.43 169.77,37.59 169.77,38.46 169.83,38.53 172.14,38.53
N13308216 on TOP (solid shape): 154.24,44.86 154.24,41.47 153.33,40.56 152.5,40.56 152.41,40.65 152.41,41.44 153.09,42.13 153.09,43.27 153.47,43.65 153.47,44.77 153.61,44.91 154.19,44.91
N13308220 on TOP (solid shape): 162.87,45.17 162.87,40.22 163.77,39.33 163.77,37.76 163.63,37.62 162.29,37.62 162.2,37.7 162.2,39.24 161.73,39.71 156.01,39.71 155.85,39.87 155.85,45.27 156.27,45.68 161.68,45.68 162.36,45.68
N13308316 on TOP (solid shape): 169.58,38.54 169.58,37.85 169.54,37.81 166.94,37.81 166.81,37.93 166.81,38.44 166.94,38.57 169.55,38.57
N13324169 on BOTTOM (solid shape): 41.35,25.36 41.35,24.61 41.18,24.45 40.6,24.45 40.31,24.17 39.2,24.17 39.07,24.3 39.07,25.06 39.17,25.16 40.16,25.16 40.49,25.49 41.22,25.49
N13350623 on TOP (solid shape): 33.13,84.29 33.13,82.74 33.03,82.64 32.44,82.64 32.32,82.77 32.32,83.6 32.32,84.29 32.46,84.43 32.99,84.43
N39955939 on TOP (solid shape): 127.05,34.82 127.05,33.35 126.99,33.3 126.33,33.3 125.91,33.72 124.72,33.72 124.58,33.86 124.58,35.36 124.8,35.57 126.3,35.57
N39956029 on TOP (solid shape): 127.04,31.85 127.04,30.49 126.74,30.19 124.82,30.19 124.64,30.37 124.64,31.42 124.85,31.63 125.58,31.63 125.85,31.9 126.99,31.9
N41042732 on TOP (solid shape): 207.99,40.38 207.99,38.3 207.92,38.23 207.25,38.23 206.86,38.62 206.86,40.75 206.93,40.82 207.55,40.82
N41500627 on TOP (solid shape): 115.73,69.23 115.8,69.2 115.83,69.12 116.21,68.72 116.59,69.12 116.62,69.2 116.69,69.23 117.24,69.23 117.4,69.07 117.4,68.38 117.18,68.16 115.12,68.16 114.78,67.82 114.64,67.82 114.59,67.87 114.59,68.96 114.85,69.23
N43454026 on TOP (solid shape): 122.21,56.93 123.17,56.93 123.25,56.85 123.25,56.32 122.92,55.99 121.09,55.99 120.9,56.19 120.9,57.18 121.01,57.29 121.85,57.29
N44372336 on TOP (solid shape): 168.85,50.51 168.85,48.55 168.92,48.49 168.92,48.25 168.75,48.08 167.8,48.08 167.76,48.12 167.76,49 167.75,49.07 167.75,50.5 167.82,50.57 168.79,50.57
N44536141 on TOP (solid shape): 122.54,59.63 122.98,59.63 123.25,59.36 123.25,58.38 123.18,58.31 122.54,58.31 121.76,59.09 121.76,59.35 121.59,59.52 121.01,59.52 120.92,59.61 120.92,60.46 121.03,60.57 121.6,60.57
N45346908 on TOP (solid shape): 135.24,21.73 136.14,21.73 136.21,21.81 136.84,21.81 136.96,21.68 136.96,21.17 136.84,21.04 130.87,21.04 130.74,21.17 130.74,21.81 130.87,21.93 135.04,21.93
N45347302 on TOP (solid shape): 179.25,36.36 179.25,34.47 179.13,34.34 177.72,34.34 177.6,34.46 177.6,35.04 177.67,35.1 177.72,35.1 177.81,35.2 177.88,35.25 177.94,35.32 178.21,35.6 178.21,36.39 178.29,36.46 179.15,36.46
N45348400 on TOP (solid shape): 178.97,40.77 178.97,39.83 179.47,39.32 179.47,37.91 179.37,37.81 178.3,37.81 178.25,37.86 178.25,38.43 177.73,38.95 177.73,40.73 177.86,40.86 178.89,40.86
N45904951 on BOTTOM (solid shape): 210.33,68.79 212.21,68.79 212.47,68.54 212.47,67.02 212.44,66.99 207.82,66.99 207.64,67.17 207.64,68.31 207.72,68.39 208.88,68.39 209.29,68.8 210.15,68.8 210.15,69.35 210.33,69.35
N46318274 on BOTTOM (solid shape): 214.23,74.6 214.23,73.62 214.18,73.57 212.14,73.57 211.66,73.09 211.66,72.71 211.4,72.45 210.34,72.45 210.09,72.7 210.09,73.95 210.86,74.73 214.1,74.73
N47519532 on BOTTOM (solid shape): 173.44,78.15 173.44,77.14 173.3,77 172.3,77 171.9,77.39 170.43,77.39 170.34,77.49 170.34,78.24 170.42,78.32 173.27,78.32
N47890230 on TOP (solid shape): 158.83,75.64 158.83,74.83 158.74,74.74 158.11,74.74 157.91,74.54 156.8,74.54 156.71,74.63 156.71,75.46 156.73,75.48 157.63,75.48 157.84,75.69 158.79,75.69
N90173610 on BOTTOM (solid shape): outline of 129 points within 212.31,65.49 221.77,72.1
N93297423 on TOP (solid shape): 168.78,79.08 168.78,76.43 168.59,76.24 167.53,76.24 167.3,76.47 167.3,78.27 166.43,79.15 166.43,79.72 166.53,79.82 168.04,79.82

Small or netless copper shapes (teardrops, artwork), in the pictures only: 64 on TOP, 42 on BOTTOM, 18 on IN1, 18 on IN3

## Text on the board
Ref Des/Silkscreen Bottom: H10 | H11 | H12 | H9 | CHB_DIS | CHA_DIS | H13 | M2X4 | H26 | L | R | NGFF | SSD
User.Comments: LA-9262P | 2014-04-10 | 2013-04-10 | VAZA0 | Win
Ref Des/Silkscreen Top: H14
GND4: GND4
GND5: GND5
BODY_CENTER: FIGURE | SIZE | 8.0 | 10.0 | 24.0 | 26.0 | 28.0 | 30.0 | 36.0 | 91.0 | 126.0 | 130.0 | 157.0 | 37.0 | 40.0 | 43.0 | 63.0 | 79.0 | 177.0 | 55.0x28.0 | 63.0x28.0 | 63.0x35.0 | 75.0x24.0 | 75.0x35.0 | 94.0x24.0 | 98.0x79.0 | DRILL CHART: TOP to BOTTOM | ALL UNITS ARE IN MILS | PLATED | NON-PLATED | QTY | 109 | 287 | 3010 | 10 | 2 | 9 | 1 | 4 | 5
USER_PART_NUM_TOP: FIGURE | SIZE | 4.0 | DRILL CHART: TOP to GND1 | ALL UNITS ARE IN MILS | PLATED | QTY | 751
DEVICE_TYPE_TOP: FIGURE | SIZE | 4.0 | DRILL CHART: GND5 to BOTTOM | ALL UNITS ARE IN MILS | PLATED | QTY | 569
USER_PART_NUM_BOTTOM: L1-TOP | L2-GND1 | L3-IN1 | L4-GND2 | L5-IN2 | L6-GND3 | L7-VCC | L8-IN3 | L9-GND4 | L10-IN4 | L11-GND5 | L12-BOT | 6.2 | 6.3 | 5.2 | 3 | 4 | 7/6 | 6.5/6 | 4/4.2 | 3/3 | 3/3.2 | 1_2mm_1+10+1(50ohm)(Top Gnd In1 Vcc In2 Vcc Gnd In3 Gnd In4 Gnd Bot)-120918.pdf
DEVICE_TYPE_BOTTOM: FIGURE | SIZE | 8.0 | DRILL CHART: GND1 to GND5 | ALL UNITS ARE IN MILS | PLATED | QTY | 890
User.26: IN5
User.45: +3VALW_EC | +3.3VDX_SSD | +LCDVDD | +5VA | GND | +VCC_CORE | +1.05VS | +1.05VA | B+ | +3VALW | +3VS | VIN
